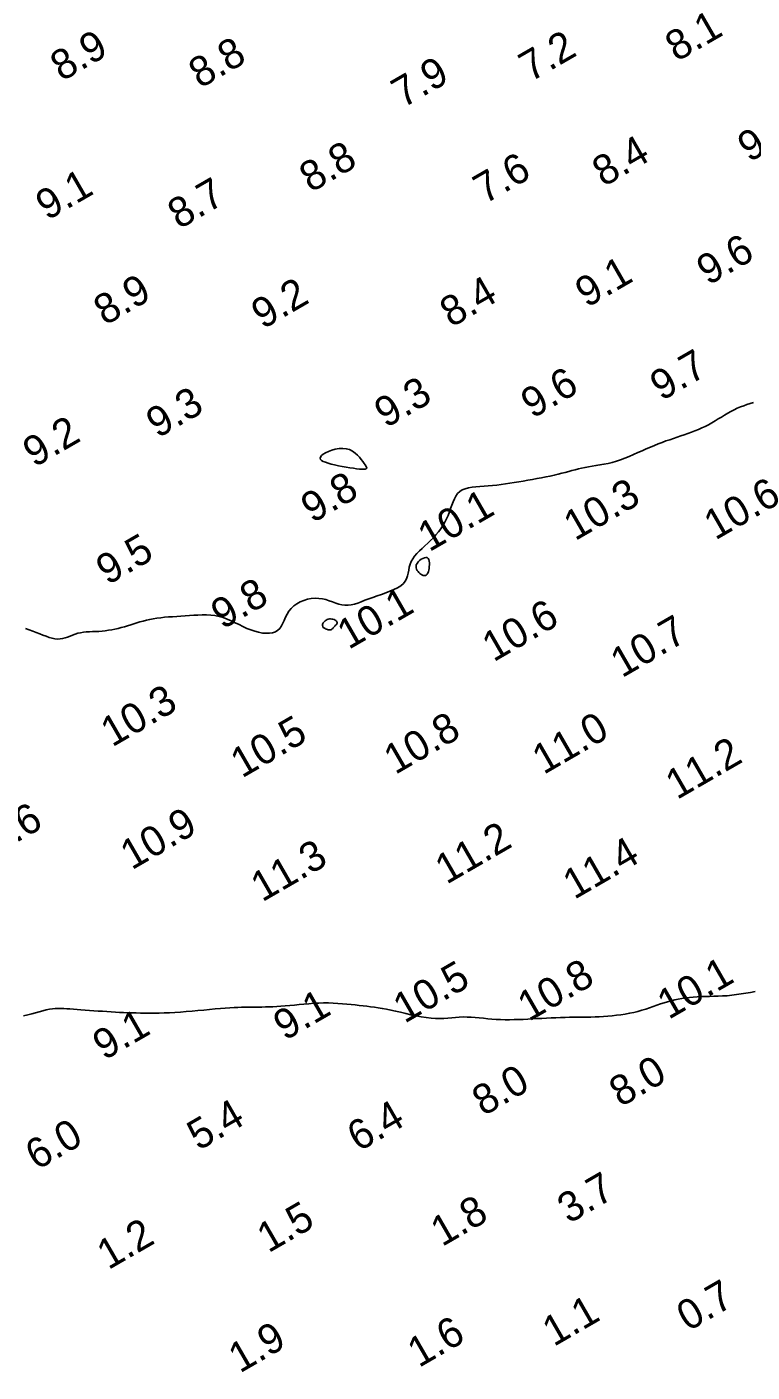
# Model space of a CAD drawing. Extents: x 3024098 to 3056816, y 418252 to 509144.
# Drawn here: x 3033611.9 to 3033733.3, y 418339.5 to 418564.6 of the extents above; entities that cross this region are included whole.
import ezdxf

# ---------------------------------------------------------------- set-up
doc = ezdxf.new("R2010")
doc.units = 0
doc.layers.add('V-CHAN-CONT-EL10', color=7, linetype='Continuous')
doc.layers.add('V-TOPO-SOUN-0911', color=7, linetype='Continuous')

msp = doc.modelspace()

# ---------------------------------------------------------------- linework, layer by layer
at = {"layer": 'V-CHAN-CONT-EL10'}
for points in [[(3033611.68, 418463.96), (3033612.29, 418463.75), (3033612.9, 418463.54), (3033613.48, 418463.32), (3033614.04, 418463.09), (3033614.59, 418462.86), (3033615.11, 418462.66), (3033615.62, 418462.47), (3033616.11, 418462.33), (3033616.58, 418462.23), (3033617.03, 418462.18), (3033617.47, 418462.21), (3033617.89, 418462.28), (3033618.3, 418462.4), (3033618.71, 418462.54), (3033619.12, 418462.71), (3033619.54, 418462.87), (3033619.97, 418463.03), (3033620.41, 418463.16), (3033620.88, 418463.26), (3033621.36, 418463.33), (3033621.85, 418463.38), (3033622.36, 418463.41), (3033622.88, 418463.44), (3033623.41, 418463.46), (3033623.95, 418463.49), (3033624.48, 418463.53), (3033625.02, 418463.59), (3033625.56, 418463.66), (3033626.1, 418463.75), (3033626.64, 418463.86), (3033627.18, 418463.98), (3033627.71, 418464.11), (3033628.24, 418464.25), (3033628.76, 418464.4), (3033629.28, 418464.56), (3033629.8, 418464.73), (3033630.31, 418464.89), (3033630.84, 418465.06), (3033631.37, 418465.21), (3033631.92, 418465.36), (3033632.48, 418465.49), (3033633.07, 418465.6), (3033633.68, 418465.7), (3033634.31, 418465.77), (3033634.96, 418465.84), (3033635.62, 418465.89), (3033636.3, 418465.93), (3033637, 418465.97), (3033637.7, 418466.01), (3033638.41, 418466.06), (3033639.12, 418466.12), (3033639.84, 418466.17), (3033640.55, 418466.22), (3033641.27, 418466.24), (3033641.98, 418466.24), (3033642.69, 418466.2), (3033643.39, 418466.12), (3033644.08, 418465.98), (3033644.76, 418465.78), (3033645.44, 418465.53), (3033646.1, 418465.24), (3033646.76, 418464.93), (3033647.42, 418464.61), (3033648.08, 418464.29), (3033648.73, 418463.99), (3033649.39, 418463.73), (3033650.05, 418463.5), (3033650.7, 418463.33), (3033651.34, 418463.21), (3033651.95, 418463.16), (3033652.52, 418463.17), (3033653.05, 418463.25), (3033653.52, 418463.42), (3033653.92, 418463.66), (3033654.26, 418463.99), (3033654.54, 418464.39), (3033654.78, 418464.84), (3033655, 418465.33), (3033655.23, 418465.84), (3033655.49, 418466.35), (3033655.79, 418466.85), (3033656.15, 418467.31), (3033656.58, 418467.73), (3033657.09, 418468.1), (3033657.65, 418468.41), (3033658.26, 418468.66), (3033658.89, 418468.85), (3033659.53, 418468.97), (3033660.18, 418469.03), (3033660.8, 418469.01), (3033661.4, 418468.93), (3033661.98, 418468.79), (3033662.54, 418468.61), (3033663.08, 418468.41), (3033663.61, 418468.22), (3033664.13, 418468.05), (3033664.64, 418467.92), (3033665.16, 418467.85), (3033665.68, 418467.85), (3033666.21, 418467.93), (3033666.75, 418468.06), (3033667.31, 418468.23), (3033667.9, 418468.44), (3033668.5, 418468.68), (3033669.14, 418468.93), (3033669.82, 418469.18), (3033670.53, 418469.43), (3033671.26, 418469.68), (3033671.99, 418469.93), (3033672.7, 418470.19), (3033673.37, 418470.47), (3033673.98, 418470.77), (3033674.51, 418471.1), (3033674.94, 418471.47), (3033675.26, 418471.87), (3033675.49, 418472.3), (3033675.64, 418472.76), (3033675.75, 418473.24), (3033675.85, 418473.73), (3033675.94, 418474.22), (3033676.07, 418474.71), (3033676.25, 418475.18), (3033676.51, 418475.64), (3033676.83, 418476.08), (3033677.21, 418476.51), (3033677.64, 418476.94), (3033678.09, 418477.36), (3033678.56, 418477.79), (3033679.04, 418478.23), (3033679.51, 418478.68), (3033679.97, 418479.15), (3033680.4, 418479.64), (3033680.81, 418480.14), (3033681.19, 418480.66), (3033681.55, 418481.2), (3033681.88, 418481.74), (3033682.17, 418482.3), (3033682.43, 418482.88), (3033682.66, 418483.46), (3033682.86, 418484.04), (3033683.06, 418484.6), (3033683.26, 418485.15), (3033683.48, 418485.66), (3033683.73, 418486.13), (3033684.02, 418486.54), (3033684.38, 418486.88), (3033684.81, 418487.15), (3033685.3, 418487.35), (3033685.85, 418487.49), (3033686.45, 418487.59), (3033687.09, 418487.67), (3033687.76, 418487.72), (3033688.45, 418487.76), (3033689.15, 418487.81), (3033689.86, 418487.88), (3033690.58, 418487.96), (3033691.3, 418488.05), (3033692.03, 418488.15), (3033692.77, 418488.27), (3033693.51, 418488.39), (3033694.26, 418488.51), (3033695.02, 418488.64), (3033695.79, 418488.78), (3033696.55, 418488.91), (3033697.32, 418489.05), (3033698.07, 418489.19), (3033698.81, 418489.33), (3033699.52, 418489.48), (3033700.21, 418489.62), (3033700.86, 418489.78), (3033701.48, 418489.93), (3033702.06, 418490.08), (3033702.63, 418490.23), (3033703.17, 418490.38), (3033703.71, 418490.53), (3033704.25, 418490.67), (3033704.8, 418490.79), (3033705.36, 418490.91), (3033705.96, 418491.02), (3033706.57, 418491.12), (3033707.2, 418491.22), (3033707.86, 418491.33), (3033708.53, 418491.45), (3033709.21, 418491.59), (3033709.91, 418491.75), (3033710.61, 418491.95), (3033711.33, 418492.19), (3033712.05, 418492.46), (3033712.77, 418492.76), (3033713.48, 418493.07), (3033714.2, 418493.39), (3033714.91, 418493.71), (3033715.61, 418494.03), (3033716.3, 418494.33), (3033716.97, 418494.6), (3033717.63, 418494.87), (3033718.28, 418495.11), (3033718.92, 418495.34), (3033719.55, 418495.56), (3033720.17, 418495.77), (3033720.78, 418495.98), (3033721.39, 418496.18), (3033721.99, 418496.39), (3033722.58, 418496.6), (3033723.18, 418496.81), (3033723.76, 418497.03), (3033724.34, 418497.27), (3033724.91, 418497.52), (3033725.48, 418497.78), (3033726.03, 418498.07), (3033726.59, 418498.37), (3033727.13, 418498.69), (3033727.67, 418499.02), (3033728.21, 418499.35), (3033728.74, 418499.67), (3033729.27, 418499.99), (3033729.8, 418500.29), (3033730.33, 418500.56), (3033730.86, 418500.81), (3033731.39, 418501.04), (3033731.93, 418501.24), (3033732.48, 418501.43), (3033733.03, 418501.6), (3033733.6, 418501.77)], [(3033733.85, 418403.2), (3033733.08, 418403.07), (3033732.29, 418402.94), (3033731.5, 418402.81), (3033730.71, 418402.7), (3033729.93, 418402.6), (3033729.15, 418402.53), (3033728.4, 418402.48), (3033727.65, 418402.45), (3033726.92, 418402.43), (3033726.2, 418402.41), (3033725.5, 418402.39), (3033724.81, 418402.37), (3033724.14, 418402.34), (3033723.48, 418402.3), (3033722.84, 418402.24), (3033722.21, 418402.17), (3033721.59, 418402.07), (3033720.98, 418401.96), (3033720.38, 418401.84), (3033719.78, 418401.69), (3033719.18, 418401.52), (3033718.59, 418401.34), (3033718, 418401.14), (3033717.4, 418400.93), (3033716.79, 418400.71), (3033716.17, 418400.49), (3033715.54, 418400.28), (3033714.89, 418400.08), (3033714.22, 418399.9), (3033713.54, 418399.73), (3033712.83, 418399.58), (3033712.11, 418399.45), (3033711.38, 418399.33), (3033710.64, 418399.24), (3033709.91, 418399.16), (3033709.18, 418399.09), (3033708.45, 418399.04), (3033707.74, 418399.01), (3033707.04, 418398.98), (3033706.34, 418398.96), (3033705.64, 418398.95), (3033704.94, 418398.95), (3033704.23, 418398.94), (3033703.51, 418398.93), (3033702.78, 418398.92), (3033702.03, 418398.9), (3033701.26, 418398.87), (3033700.49, 418398.84), (3033699.7, 418398.81), (3033698.91, 418398.77), (3033698.12, 418398.73), (3033697.33, 418398.69), (3033696.54, 418398.65), (3033695.76, 418398.61), (3033694.99, 418398.57), (3033694.23, 418398.54), (3033693.47, 418398.52), (3033692.72, 418398.51), (3033691.97, 418398.51), (3033691.23, 418398.53), (3033690.5, 418398.56), (3033689.77, 418398.61), (3033689.06, 418398.67), (3033688.35, 418398.74), (3033687.64, 418398.81), (3033686.95, 418398.88), (3033686.27, 418398.93), (3033685.6, 418398.96), (3033684.95, 418398.97), (3033684.31, 418398.94), (3033683.68, 418398.9), (3033683.05, 418398.84), (3033682.4, 418398.78), (3033681.74, 418398.73), (3033681.06, 418398.71), (3033680.34, 418398.71), (3033679.58, 418398.76), (3033678.78, 418398.85), (3033677.94, 418398.99), (3033677.08, 418399.16), (3033676.2, 418399.34), (3033675.33, 418399.55), (3033674.47, 418399.75), (3033673.64, 418399.95), (3033672.85, 418400.12), (3033672.11, 418400.27), (3033671.41, 418400.4), (3033670.74, 418400.51), (3033670.1, 418400.6), (3033669.46, 418400.68), (3033668.84, 418400.76), (3033668.2, 418400.83), (3033667.56, 418400.9), (3033666.88, 418400.97), (3033666.19, 418401.05), (3033665.46, 418401.12), (3033664.73, 418401.19), (3033663.97, 418401.24), (3033663.19, 418401.29), (3033662.4, 418401.31), (3033661.59, 418401.31), (3033660.77, 418401.29), (3033659.95, 418401.25), (3033659.12, 418401.19), (3033658.3, 418401.12), (3033657.49, 418401.04), (3033656.69, 418400.96), (3033655.92, 418400.89), (3033655.17, 418400.82), (3033654.45, 418400.76), (3033653.77, 418400.72), (3033653.1, 418400.68), (3033652.47, 418400.66), (3033651.85, 418400.64), (3033651.25, 418400.62), (3033650.68, 418400.62), (3033650.11, 418400.61), (3033649.55, 418400.61), (3033649, 418400.6), (3033648.43, 418400.6), (3033647.85, 418400.59), (3033647.24, 418400.57), (3033646.59, 418400.54), (3033645.89, 418400.5), (3033645.13, 418400.45), (3033644.3, 418400.38), (3033643.42, 418400.3), (3033642.49, 418400.22), (3033641.53, 418400.12), (3033640.55, 418400.03), (3033639.56, 418399.94), (3033638.58, 418399.86), (3033637.62, 418399.79), (3033636.69, 418399.73), (3033635.79, 418399.68), (3033634.91, 418399.65), (3033634.07, 418399.62), (3033633.25, 418399.61), (3033632.45, 418399.61), (3033631.68, 418399.61), (3033630.93, 418399.62), (3033630.2, 418399.64), (3033629.49, 418399.66), (3033628.79, 418399.68), (3033628.1, 418399.71), (3033627.41, 418399.74), (3033626.71, 418399.78), (3033626.01, 418399.82), (3033625.3, 418399.86), (3033624.57, 418399.91), (3033623.83, 418399.95), (3033623.09, 418400), (3033622.36, 418400.05), (3033621.65, 418400.1), (3033620.96, 418400.16), (3033620.3, 418400.21), (3033619.68, 418400.26), (3033619.11, 418400.31), (3033618.58, 418400.35), (3033618.08, 418400.39), (3033617.6, 418400.41), (3033617.13, 418400.41), (3033616.65, 418400.39), (3033616.17, 418400.35), (3033615.67, 418400.27), (3033615.14, 418400.16), (3033614.58, 418400.02), (3033613.98, 418399.85), (3033613.36, 418399.68), (3033612.71, 418399.5), (3033612.04, 418399.32), (3033611.33, 418399.15)]]:
    msp.add_lwpolyline(points, dxfattribs=at)
for points in [[(3033662.34, 418491.62), (3033661.89, 418491.77), (3033661.53, 418491.92), (3033661.25, 418492.09), (3033661.07, 418492.27), (3033661, 418492.46), (3033661.04, 418492.66), (3033661.21, 418492.89), (3033661.5, 418493.13), (3033661.91, 418493.37), (3033662.4, 418493.6), (3033662.96, 418493.81), (3033663.55, 418493.97), (3033664.17, 418494.08), (3033664.78, 418494.1), (3033665.37, 418494.04), (3033665.91, 418493.89), (3033666.4, 418493.64), (3033666.85, 418493.33), (3033667.25, 418492.98), (3033667.6, 418492.61), (3033667.9, 418492.25), (3033668.15, 418491.9), (3033668.36, 418491.6), (3033668.52, 418491.36), (3033668.64, 418491.17), (3033668.72, 418491.04), (3033668.78, 418490.94), (3033668.8, 418490.87), (3033668.81, 418490.82), (3033668.81, 418490.79), (3033668.79, 418490.76), (3033668.77, 418490.73), (3033668.74, 418490.69), (3033668.68, 418490.66), (3033668.58, 418490.63), (3033668.44, 418490.61), (3033668.23, 418490.61), (3033667.94, 418490.62), (3033667.58, 418490.65), (3033667.11, 418490.7), (3033666.58, 418490.77), (3033665.98, 418490.85), (3033665.35, 418490.96), (3033664.7, 418491.07), (3033664.06, 418491.2), (3033663.43, 418491.34), (3033662.85, 418491.47)], [(3033677.06, 418474.36), (3033677.08, 418474.12), (3033677.15, 418473.9), (3033677.26, 418473.69), (3033677.4, 418473.5), (3033677.56, 418473.33), (3033677.72, 418473.18), (3033677.88, 418473.06), (3033678.02, 418472.97), (3033678.15, 418472.9), (3033678.25, 418472.85), (3033678.35, 418472.82), (3033678.44, 418472.81), (3033678.52, 418472.81), (3033678.59, 418472.83), (3033678.66, 418472.85), (3033678.74, 418472.89), (3033678.81, 418472.93), (3033678.88, 418473), (3033678.95, 418473.08), (3033679.01, 418473.19), (3033679.08, 418473.34), (3033679.14, 418473.52), (3033679.19, 418473.75), (3033679.24, 418474.02), (3033679.28, 418474.32), (3033679.3, 418474.64), (3033679.3, 418474.95), (3033679.27, 418475.24), (3033679.2, 418475.5), (3033679.09, 418475.69), (3033678.93, 418475.82), (3033678.72, 418475.85), (3033678.47, 418475.81), (3033678.2, 418475.7), (3033677.92, 418475.54), (3033677.66, 418475.34), (3033677.43, 418475.11), (3033677.24, 418474.86), (3033677.11, 418474.6)], [(3033663.45, 418464.34), (3033663.54, 418464.44), (3033663.64, 418464.55), (3033663.72, 418464.65), (3033663.79, 418464.76), (3033663.83, 418464.86), (3033663.85, 418464.97), (3033663.82, 418465.08), (3033663.75, 418465.18), (3033663.64, 418465.28), (3033663.5, 418465.37), (3033663.33, 418465.45), (3033663.14, 418465.51), (3033662.95, 418465.55), (3033662.75, 418465.57), (3033662.55, 418465.56), (3033662.35, 418465.52), (3033662.18, 418465.46), (3033662.01, 418465.37), (3033661.86, 418465.27), (3033661.72, 418465.15), (3033661.61, 418465.03), (3033661.52, 418464.9), (3033661.45, 418464.78), (3033661.41, 418464.66), (3033661.39, 418464.55), (3033661.4, 418464.44), (3033661.43, 418464.34), (3033661.48, 418464.25), (3033661.54, 418464.16), (3033661.63, 418464.08), (3033661.73, 418464.01), (3033661.84, 418463.94), (3033661.96, 418463.88), (3033662.09, 418463.83), (3033662.22, 418463.79), (3033662.35, 418463.76), (3033662.48, 418463.74), (3033662.6, 418463.73), (3033662.71, 418463.74), (3033662.81, 418463.76), (3033662.89, 418463.8), (3033662.97, 418463.85), (3033663.04, 418463.92), (3033663.12, 418463.99), (3033663.19, 418464.07), (3033663.27, 418464.15), (3033663.35, 418464.25)]]:
    msp.add_lwpolyline(points, close=True, dxfattribs=at)

# ---------------------------------------------------------------- texts
at = {"layer": 'V-TOPO-SOUN-0911'}
for s, p in [('8.1', (3033720.7, 418558.72)), ('8.9', (3033617.74, 418555.43)), ('7.2', (3033696.21, 418555.33)), ('8.8', (3033640.9, 418554.25)), ('7.9', (3033674.86, 418550.97)), ('9.3', (3033732.83, 418541.88)), ('8.8', (3033659.44, 418536.83)), ('8.4', (3033708.48, 418537.78)), ('7.6', (3033688.57, 418534.9)), ('9.1', (3033615.29, 418532.15)), ('8.7', (3033637.39, 418530.69)), ('9.6', (3033725.97, 418521.28)), ('9.1', (3033705.64, 418517.55)), ('8.9', (3033624.99, 418514.58)), ('8.4', (3033682.96, 418514.25)), ('9.2', (3033651.4, 418513.96)), ('9.7', (3033718.16, 418501.95)), ('9.6', (3033696.54, 418499)), ('9.3', (3033672, 418497.42)), ('9.3', (3033633.78, 418495.72)), ('9.2', (3033613.14, 418490.83)), ('9.8', (3033659.7, 418481.51)), ('10.3 ', (3033703.69, 418478.55)), ('10.6 ', (3033727.18, 418478.66)), ('10.1 ', (3033679.27, 418476.7)), ('9.5', (3033625.4, 418471.14)), ('9.8', (3033644.64, 418463.73)), ('10.1 ', (3033665.78, 418460.36)), ('10.6 ', (3033690.04, 418458.28)), ('10.7 ', (3033711.54, 418455.62)), ('10.3 ', (3033626.17, 418444.04)), ('10.5 ', (3033647.91, 418438.85)), ('10.8 ', (3033673.58, 418439.44)), ('11.0 ', (3033698.43, 418439.44)), ('11.2 ', (3033720.76, 418435.24)), ('10.6 ', (3033603.59, 418424.29)), ('10.9 ', (3033629.45, 418423.47)), ('11.2 ', (3033682.17, 418421.07)), ('11.3 ', (3033651.3, 418418.12)), ('11.4 ', (3033703.56, 418418.54)), ('10.5 ', (3033675.14, 418397.81)), ('10.8 ', (3033695.98, 418398.14)), ('10.1 ', (3033719.36, 418398.45)), ('9.1', (3033655.09, 418394.91)), ('9.1', (3033624.84, 418391.63)), ('8.0', (3033711.32, 418383.81)), ('8.0', (3033688.36, 418382.3)), ('5.4', (3033640.64, 418376.52)), ('6.4', (3033667.44, 418376.33)), ('6.0', (3033613.55, 418373.24)), ('3.7', (3033702.64, 418364.29)), ('1.5', (3033652.34, 418359.4)), ('1.8', (3033681.42, 418360.45)), ('1.2', (3033625.54, 418356.58)), ('0.7', (3033722.62, 418346.27)), ('1.1', (3033700.13, 418343.73)), ('1.9', (3033647.56, 418339.29)), ('1.6', (3033677.54, 418340.21))]:
    msp.add_text(s, height=5, rotation=30, dxfattribs=at).set_placement(p)

doc.saveas('drawing.dxf')
